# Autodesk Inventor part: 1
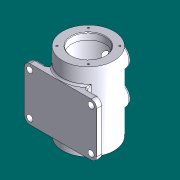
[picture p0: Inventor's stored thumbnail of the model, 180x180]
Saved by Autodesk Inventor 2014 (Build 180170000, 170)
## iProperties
Created: 2014-12
Part Number: 1
Material: 일반
Document SubType Name: Modeling
Designer: user
Density: 1 g/cm^3
Appearance: PTFE
Author: user
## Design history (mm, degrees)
sketch "스케치22"
  geometry: C1 r 46 at (0, 0); 1 further point
  constraints: 1 centre point, 1 coincident
  dimensions: "d39" = 92 diameter of C1
extrude "돌출20" new body sketch "스케치22" distance "d40" = 140; taper "d41" = 0 deg
sketch "스케치23"
  geometry: C1 r 46 at (0, 0) reference; C2 r 30 at (0, 0)
  constraints: 1 centre point, 1 coincident
  dimensions: "d42" = 60 diameter of C2
extrude "돌출21" cut sketch "스케치23" distance "d43" = 140; taper "d44" = 0 deg
node "작업 평면1"
sketch "스케치24"
  geometry: C1 r 37.5 at (0, 0); 1 further point
  constraints: 1 centre point, 1 coincident
  dimensions: "d46" = 75 diameter of C1
extrude "돌출22" cut sketch "스케치24" distance "d47" = 116; taper "d48" = 0 deg
sketch "스케치25"
  geometry: L1 (56, 120)-(25, 120); L2 (25, 120)-(25, 100); L3 (25, 100)-(56, 100); L4 (56, 100)-(56, 120); L5 (46, 140)-(-46, 140) reference; L6 (56, 40)-(0, 40); L7 (0, 40)-(0, 20); L8 (0, 20)-(56, 20); L9 (56, 20)-(56, 40); 1 further point
  constraints: 16 end point, 4 parallel, 2 horizontal, 2 perpendicular
  dimensions: "d49" = 40 distance between parallel lines of L5 L3; "d50" = 20 distance of L3.end L1.start; "d51" = 20 distance of L7.end L6.end; "d52" = 60 distance between parallel lines of L3 L6; "d53" = 0 distance from line of point (0, 0) L7; "d54" = 56 distance from line of point (0, 0) L9; "d55" = 56 distance between parallel lines of L7 L4
revolve "회전1" stored, may be unused: angle "d56" = 90 deg
revolve "회전2" stored, may be unused: angle "d57" = 90 deg
feature "면 삭제1"
node "작업 평면2"
sketch "스케치26"
  geometry: L1 (0, -50)-(65, -50); L2 (65, -50)-(65, -38); L3 (65, -38)-(0, -38); L4 (0, -38)-(0, -50); L5 (0, -38)-(-65, -38); L6 (-65, -38)-(-65, -50); L7 (-65, -50)-(0, -50); L8 (0, -50)-(0, -38); 1 further point
  constraints: 16 end point, 4 parallel, 2 horizontal, 2 perpendicular
  dimensions: "d59" = 12 distance of L2.end L1.end; "d60" = 65 distance of L2.end L3.end; "d61" = 0 distance from line of point (0, 0) L4; "d62" = 65 distance of L7.end L6.end; "d63" = 12 distance of L6.end L5.end; "d65" = 50 distance from line of point (0, 0) L1
extrude "돌출23" join sketch "스케치26" distance "d66" = 95; taper "d67" = 0 deg
fillet "모깎기1" dims "d68" = 10
fillet "모깎기2" dims "d69" = 5
fillet "모깎기3" dims "d70" = 3
fillet "모깎기4" dims "d71" = 3
sketch "스케치27"
  geometry: C1 r 17 at (0, 0) reference; C2 r 15 at (0, 0); C3 r 17 at (0, -60) reference; C4 r 17 at (0, 0) reference; C5 r 15 at (0, -60); 1 further point
  constraints: 2 centre point, 2 coincident
  dimensions: "d72" = 30 diameter of C2; "d73" = 30 diameter of C5
extrude "돌출24" cut sketch "스케치27" distance "d74" = 8; taper "d75" = 0 deg
sketch "스케치28"
  geometry: C1 r 15 at (0, 0) reference; C2 r 12.5 at (0, 0); C3 r 15 at (0, 60) reference; C4 r 15 at (0, 0) reference; C5 r 12.5 at (0, 60); A1 r 20 centre (0, 0) between (8.564, -18.074) and (8.564, 18.074) reference; A2 r 20 centre (0, 0) between (-8.564, 18.074) and (-8.564, -18.074) reference; A3 r 20 centre (0, 60) between (8.564, 41.926) and (8.564, 78.074) reference; A4 r 20 centre (0, 60) between (-8.564, 78.074) and (-8.564, 41.926) reference; 1 further point
  constraints: 4 horizontal alignment, 2 centre point, 2 coincident
  dimensions: "d76" = 25 diameter of C2; "d77" = 25 diameter of C5
extrude "돌출25" cut sketch "스케치28" distance "d78" = 50; taper "d79" = 0 deg
fillet "모깎기5" dims "d80" = 3
sketch "스케치29"
  geometry: L1 (0, 0)-(28.284, 28.284); L2 (0, 0)-(40, 0); C1 r 46 at (0, 0) reference
  constraints: 4 end point, 1 equal length, 1 horizontal
  dimensions: "d81" = 40 distance of L1.start L1.end; "d82" = 45 deg angle of L2 L1
hole "구멍1" sketch "스케치29" at (28.284, 28.284) diameter "d83" = 3.242; stored, may be unused: countersink angle "d87" = 90 deg, drill point angle "d89" = 118 deg; dims "d84" = 8, "d85" = 4, "d86" = 2, "d88" = 10
node "작업 평면3"
sketch "스케치31"
  geometry: L1 (10, 85)-(26.116, 85) reference; L2 (26.116, 85)-(34.065, 85) reference; L3 (39.077, 88)-(39.077, 100) reference; L4 (39.077, 100)-(90.923, 100) reference; L5 (90.923, 100)-(90.923, 88) reference; L6 (95.935, 85)-(103.884, 85) reference; L7 (103.884, 85)-(120, 85) reference; L8 (130, 75)-(130, 0) reference; L9 (120, -10)-(103.884, -10) reference; L10 (103.884, 85)-(103.884, -10) reference; L11 (0, 0)-(0, 75) reference; L12 (26.116, -10)-(10, -10) reference; L13 (34.065, -10)-(26.116, -10) reference; L14 (39.077, -40)-(39.077, -13) reference; L15 (90.923, -40)-(39.077, -40) reference; L16 (90.923, -13)-(90.923, -40) reference; L17 (103.884, -10)-(95.935, -10) reference; L18 (26.116, -10)-(26.116, 85) reference; C1 r 5.5 at (10, 0); C2 r 5.5 at (10, 75); A1 r 10 centre (120, 75) between (130, 75) and (120, 85) reference; A2 r 10 centre (120, 0) between (120, -10) and (130, 0) reference; A3 r 10 centre (10, 75) between (10, 85) and (0, 75) reference; A4 r 10 centre (10, 0) between (0, 0) and (10, -10) reference; 1 further point
  constraints: 2 centre point, 2 coincident, 4 other
  dimensions: "d93" = 11 diameter of C1; "d94" = 11 diameter of C2
extrude "돌출26" cut sketch "스케치31" distance "d95" = 50; taper "d96" = 0 deg
fillet "모깎기6" dims "d97" = 3
chamfer "모따기1" distance "d98" = 1; stored, may be unused: second distance "d99" = 2, angle "d100" = 45 deg
sketch "스케치32"
  geometry: L1 (-146.62, 21.526)-(-146.62, 102.293); L2 (-146.62, 102.293)-(182.748, 102.293); L3 (182.748, 102.293)-(182.748, 21.526); L4 (182.748, 21.526)-(-146.62, 21.526); L5 (26.116, 7)-(26.116, 82) reference; A1 r 7 centre (16.116, 7) between (16.116, 0) and (23.116, 7) reference; 2 further points
  constraints: 2 other
  dimensions: "d101" = 8 distance from line of point (18.116, 42) L5; "d102" = 35 vertical distance of point (18.116, 42) A1.centre
extrude "돌출27" join sketch "스케치32" distance "d103" = 1; taper "d104" = 0 deg
node "솔리드18"
pattern_circular "원형 패턴1" dims angle "d91" = 360 deg
mirror "대칭1"
mirror "대칭2"
node "절단 모서리 투영1"
node "절단 모서리 투영2"
node "절단 모서리 투영3"
other parameters: "d45" = -12, "d58" = -15
